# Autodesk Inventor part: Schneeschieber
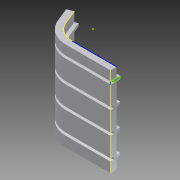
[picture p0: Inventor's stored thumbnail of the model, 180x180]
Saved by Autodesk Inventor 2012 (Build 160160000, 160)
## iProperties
Created: 2013-01
Part Number: Schneeschieber
Material: Default
Document SubType Name: Modeling
Designer: Hans-Jürgen
Density: 1 g/cm^3
Author: Hans-Jürgen
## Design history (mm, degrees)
sketch "Skizze1"
  geometry: L1 (0, 0)-(-10.002, 0); L2 (-15.649, 3.82)-(-16.896, 6.931); L3 (0, 1.399)-(-10.002, 1.399); L4 (-14.35, 4.341)-(-15.597, 7.452); L5 (-15.597, 7.452)-(-16.896, 6.931); L6 (0, 1.399)-(0, 0); A1 r 6.084 centre (-10.002, 6.084) between (-15.649, 3.82) and (-10.002, 0); A2 r 4.684 centre (-10.002, 6.084) between (-14.35, 4.341) and (-10.002, 1.399)
  constraints: 12 end point, 4 point on circle, 2 centre point, 2 perpendicular, 2 tangent, 1 horizontal, 2 other
extrude "Extrusion1" new body sketch "Skizze1" distance "d0" = 20; taper "d1" = 0 deg
sketch "Skizze3"
  geometry: L1 (-10.002, 1.399)-(0, 1.399); L2 (-15.597, 7.452)-(-14.35, 4.341) reference; A1 r 4.684 centre (-10.002, 6.084) between (-14.35, 4.341) and (-10.002, 1.399) reference
  constraints: 2 end point
sketch "Skizze4"
  geometry: L1 (-17.874, 2.15)-(-17.253, 2.15); L2 (-17.253, 2.15)-(-17.253, 0.7); L3 (-17.253, 0.7)-(-17.874, 0.7); L4 (-17.874, 0.7)-(-17.874, 2.15); L5 (0, 0)-(-20, 0) reference; L6 (-17.874, 0.7)-(-17.253, 0.7); L7 (-17.253, 0.7)-(-17.253, 0); L8 (-17.253, 0)-(-17.874, 0); L9 (-17.874, 0)-(-17.874, 0.7)
  constraints: 16 end point, 4 parallel, 2 horizontal, 2 perpendicular, 1 point on line
feature "Sweeping1" dims "d2" = 0
sketch "3D-Skizze2"
feature "Sweeping2" sketch "3D-Skizze2" dims "d3" = 0
pattern_linear "Rechteckige Anordnung1" dims "d6" = 5
node "Volumenkörper1"
